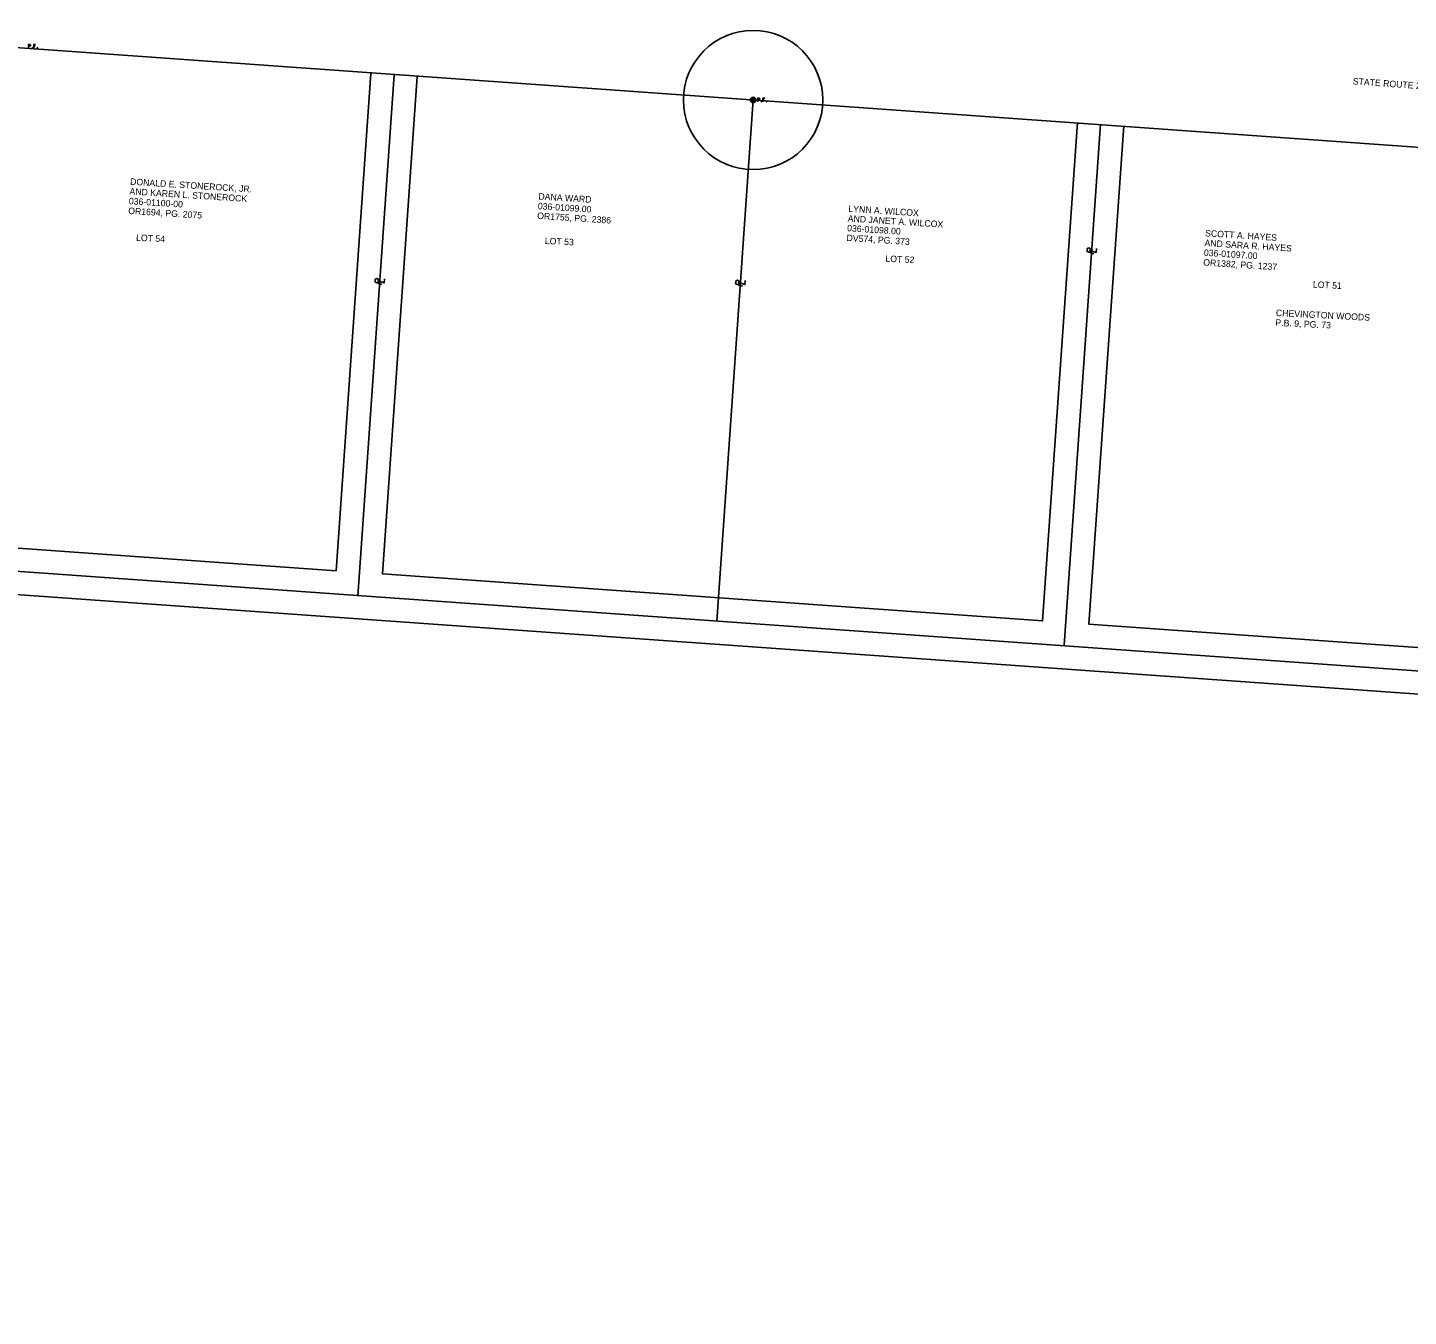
# Model space of a CAD drawing. Extents: x 1898254 to 1901377, y 701554 to 704886.
# Drawn here: x 1898855 to 1899450, y 702722 to 703277 of the extents above; entities that cross this region are included whole.
import ezdxf

# ---------------------------------------------------------------- set-up
doc = ezdxf.new("R2010")
doc.units = 0
for name, color, linetype in [('DV_X_Property_Line', 7, 'Continuous'), ('DV_X_Text', 7, 'Continuous'), ('RW_X_Esmt_General', 7, 'Continuous'), ('RW_X_Esmt_U', 7, 'Continuous'), ('RW_X_Fee_RW', 7, 'Continuous'), ('RW_X_Text', 7, 'Continuous'), ('SC_Scratch1', 7, 'Continuous'), ('SC_Scratch2', 7, 'Continuous'), ('SC_Scratch5', 7, 'Continuous'), ('SV_X_Mon_Cells_Found', 7, 'Continuous')]:
    doc.layers.add(name, color=color, linetype=linetype)

msp = doc.modelspace()

# ---------------------------------------------------------------- linework, layer by layer
at = {"layer": 'DV_X_Property_Line'}
for p, q in [((1898997.3, 703032.17), (1899012.93, 703256.63)), ((1899151.93, 703021.4), (1899167.56, 703245.86)), ((1899301.56, 703010.98), (1899317.2, 703235.44)), ((1899312.72, 703180.1), (1899312.81, 703181.4)), ((1899313.4, 703180.86), (1899313.4, 703180.86)), ((1899006.06, 703166.95), (1899006.15, 703168.25)), ((1899006.74, 703167.71), (1899006.74, 703167.71)), ((1899161.39, 703166.22), (1899161.48, 703167.51)), ((1899162.06, 703166.97), (1899162.06, 703166.97)), ((1899469, 702998.85), (1898413.79, 703073.89))]:
    msp.add_line(p, q, dxfattribs=at)
for points in [[(1899314.28, 703179.58), (1899311.37, 703180.56), (1899311.45, 703181.59)], [(1899312.46, 703181.19), (1899315.35, 703180.2), (1899315.47, 703181.94)], [(1899007.62, 703166.42), (1899004.72, 703167.41), (1899004.79, 703168.44)], [(1899005.8, 703168.04), (1899008.7, 703167.05), (1899008.82, 703168.79)], [(1899162.95, 703165.69), (1899160.04, 703166.67), (1899160.12, 703167.7)], [(1899161.13, 703167.31), (1899164.02, 703166.31), (1899164.14, 703168.05)]]:
    msp.add_lwpolyline(points, dxfattribs=at)
for centre in [(1899312.12, 703181.44), (1899005.46, 703168.29), (1899160.79, 703167.55)]:
    msp.add_arc(centre, 0.69, 356.48684, 167.34395, dxfattribs=at)
at = {"layer": 'RW_X_Esmt_General'}
msp.add_lwpolyline([(1898728.62, 703276.43), (1898713.73, 703062.59), (1898988.04, 703043.08)], dxfattribs=at)
at = {"layer": 'RW_X_Esmt_U'}
msp.add_line((1898988.04, 703043.08), (1899002.96, 703257.32), dxfattribs=at)
for points in [[(1899022.91, 703255.93), (1899007.99, 703041.66), (1899292.27, 703021.45), (1899307.22, 703236.13)], [(1899327.17, 703234.74), (1899312.22, 703020.03), (1899459.74, 703009.54), (1899474.99, 703224)], [(1898413.09, 703063.91), (1899458.32, 702989.59), (1899455.83, 702954.62), (1899530.23, 702949.35), (1899466.62, 702051.43)]]:
    msp.add_lwpolyline(points, dxfattribs=at)
at = {"layer": 'RW_X_Fee_RW'}
msp.add_line((1898449.4, 703296.93), (1899763.77, 703203.46), dxfattribs=at)
at = {"layer": 'SC_Scratch1'}
msp.add_circle((1899167.56, 703245.86), 30, dxfattribs=at)
at = {"layer": 'SC_Scratch2'}
msp.add_circle((1899815.76, 703229.84), 1561.35, dxfattribs=at)
at = {"layer": 'SC_Scratch5'}
msp.add_line((1898449.4, 703296.93), (1899763.77, 703203.46), dxfattribs=at)
at = {"layer": 'SV_X_Mon_Cells_Found'}
for points in [[(1898855.47, 703268.22), (1898855.47, 703269.82), (1898856, 703269.82), (1898856.06, 703269.8), (1898856.14, 703269.78), (1898856.17, 703269.75), (1898856.2, 703269.73), (1898856.25, 703269.67), (1898856.28, 703269.6), (1898856.3, 703269.5), (1898856.3, 703269.35), (1898856.29, 703269.3), (1898856.27, 703269.22), (1898856.22, 703269.14), (1898856.18, 703269.1), (1898856.15, 703269.07), (1898856.09, 703269.05), (1898856, 703269.04), (1898855.47, 703269.04)], [(1898858.48, 703269.82), (1898857.72, 703269.82), (1898857.72, 703268.22)], [(1898857.12, 703268.43), (1898857.17, 703268.43), (1898857.2, 703268.41), (1898857.24, 703268.36), (1898857.24, 703268.29), (1898857.2, 703268.24), (1898857.17, 703268.22), (1898857.12, 703268.22), (1898857.08, 703268.24), (1898857.05, 703268.29), (1898857.05, 703268.36), (1898857.08, 703268.41), (1898857.12, 703268.43)], [(1898857.72, 703269.04), (1898858.26, 703269.04)], [(1898859.27, 703268.43), (1898859.32, 703268.43), (1898859.35, 703268.41), (1898859.39, 703268.36), (1898859.39, 703268.29), (1898859.35, 703268.24), (1898859.32, 703268.22), (1898859.27, 703268.22), (1898859.23, 703268.24), (1898859.2, 703268.29), (1898859.2, 703268.36), (1898859.23, 703268.41), (1898859.27, 703268.43)], [(1899169.56, 703245.06), (1899169.56, 703246.66), (1899170.09, 703246.66), (1899170.14, 703246.64), (1899170.22, 703246.62), (1899170.25, 703246.59), (1899170.28, 703246.57), (1899170.33, 703246.51), (1899170.36, 703246.44), (1899170.38, 703246.34), (1899170.38, 703246.19), (1899170.37, 703246.14), (1899170.35, 703246.07), (1899170.31, 703245.98), (1899170.26, 703245.94), (1899170.23, 703245.91), (1899170.17, 703245.89), (1899170.09, 703245.88), (1899169.56, 703245.88)], [(1899172.57, 703246.66), (1899171.8, 703246.66), (1899171.8, 703245.06)], [(1899171.8, 703245.88), (1899172.34, 703245.88)], [(1899171.2, 703245.27), (1899171.25, 703245.27), (1899171.29, 703245.25), (1899171.32, 703245.2), (1899171.32, 703245.13), (1899171.29, 703245.08), (1899171.25, 703245.06), (1899171.2, 703245.06), (1899171.17, 703245.08), (1899171.13, 703245.13), (1899171.13, 703245.2), (1899171.17, 703245.25), (1899171.2, 703245.27)], [(1899173.35, 703245.27), (1899173.4, 703245.27), (1899173.44, 703245.25), (1899173.47, 703245.2), (1899173.47, 703245.13), (1899173.44, 703245.08), (1899173.4, 703245.06), (1899173.35, 703245.06), (1899173.31, 703245.08), (1899173.28, 703245.13), (1899173.28, 703245.2), (1899173.31, 703245.25), (1899173.35, 703245.27)]]:
    msp.add_lwpolyline(points, dxfattribs=at)
for radius in [1.2, 0.495]:
    msp.add_circle((1899167.56, 703245.86), radius, dxfattribs=at)

# ---------------------------------------------------------------- texts
at = {"layer": 'DV_X_Text'}
for s, rotation, p in [('DONALD E. STONEROCK, JR.', 356.3351, (1898899.15, 703209.36)), ('AND KAREN L. STONEROCK', 356.3351, (1898898.88, 703205.17)), ('DANA WARD', 356.3351, (1899075.02, 703203.02)), ('OR1694, PG. 2075', 356.3351, (1898898.34, 703196.79)), ('036-01100-00', 356.3351, (1898898.61, 703200.98)), ('036-01099.00', 356.3351, (1899074.76, 703198.83)), ('LYNN A. WILCOX', 356.3351, (1899208.52, 703197.7)), ('OR1755, PG. 2386', 356.3351, (1899074.49, 703194.64)), ('036-01098.00', 356.3351, (1899207.98, 703189.32)), ('AND JANET A. WILCOX', 356.3351, (1899208.25, 703193.51)), ('LOT 54', 357.09486, (1898901.73, 703185.21)), ('LOT 53', 357.09486, (1899077.78, 703183.83)), ('DV574, PG. 373', 356.3351, (1899207.72, 703185.13)), ('SCOTT A. HAYES', 356.3351, (1899362.17, 703187.13)), ('036-01097.00', 356.3351, (1899361.64, 703178.75)), ('AND SARA R. HAYES', 356.3351, (1899361.91, 703182.94)), ('LOT 52', 357.09486, (1899224.48, 703176.19)), ('OR1382, PG. 1237', 356.3351, (1899361.37, 703174.56)), ('LOT 51', 357.09486, (1899408.6, 703165.06)), ('P.B. 9, PG. 73', 357.09486, (1899392.46, 703148.62)), ('CHEVINGTON WOODS', 357.09486, (1899392.67, 703152.81))]:
    msp.add_text(s, height=2.8, rotation=rotation, dxfattribs=at).set_placement(p)
at = {"layer": 'RW_X_Text'}
msp.add_text('STATE ROUTE 204 (BLACKLICK-EASTERN ROAD) (VARIES)', height=2.8, rotation=355.93252, dxfattribs=at).set_placement((1899425.77, 703252.61))

doc.saveas('drawing.dxf')
